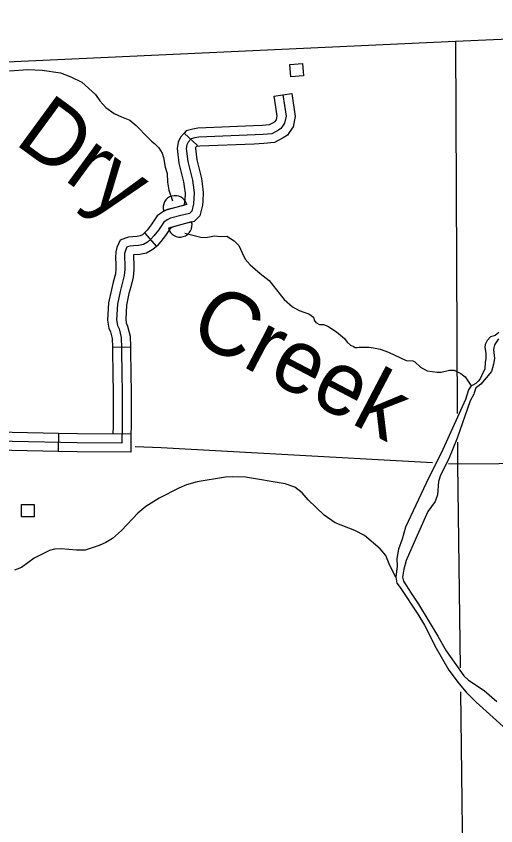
# Model space of a CAD drawing. Extents: x 1369885 to 1370219, y 379980 to 380218.
# Drawn here: x 1370011.52 to 1370027.37, y 380094.55 to 380121.32 of the extents above; entities that cross this region are included whole.
import ezdxf

# ---------------------------------------------------------------- set-up
doc = ezdxf.new("R2010")
doc.units = 0
for name, color, linetype in [('Level 1', 7, 'Continuous'), ('Level 32', 7, 'Continuous'), ('Level 35', 7, 'Continuous'), ('Level 38', 7, 'Continuous'), ('Level 45', 7, 'Continuous'), ('Level 5', 7, 'Continuous'), ('Level 56', 7, 'Continuous')]:
    doc.layers.add(name, color=color, linetype=linetype)

msp = doc.modelspace()

# ---------------------------------------------------------------- linework, layer by layer
at = {"layer": 'Level 1'}
msp.add_lwpolyline([(1370004.498, 380119.502), (1370026.044, 380120.496), (1370044.91, 380121.323)], dxfattribs=at)
at = {"layer": 'Level 32'}
for p, q in [((1370012.919, 380107.526), (1370012.907, 380106.93)), ((1370015.315, 380107.499), (1370015.307, 380106.903))]:
    msp.add_line(p, q, dxfattribs=at)
for points in [[(1370012.919, 380107.526), (1370011.391, 380107.558), (1370010.822, 380107.575)], [(1370015.013, 380107.203), (1370013.539, 380107.215), (1370011.383, 380107.259), (1370008.599, 380107.343), (1370005.817, 380107.471), (1370004.191, 380107.531)], [(1370015.315, 380107.499), (1370013.543, 380107.514), (1370012.919, 380107.526)], [(1370012.907, 380106.93), (1370011.376, 380106.961), (1370010.804, 380106.978)], [(1370015.307, 380106.903), (1370013.534, 380106.917), (1370012.907, 380106.93)]]:
    msp.add_lwpolyline(points, dxfattribs=at)
at = {"layer": 'Level 35'}
for points in [[(1370011.296, 380119.518), (1370011.905, 380119.565), (1370012.381, 380119.54), (1370012.986, 380119.45), (1370013.33, 380119.314), (1370013.685, 380119.146), (1370014.138, 380118.737), (1370014.281, 380118.523), (1370014.48, 380118.299), (1370014.76, 380118.107), (1370015, 380117.995), (1370015.28, 380117.88), (1370015.488, 380117.704), (1370015.871, 380117.316), (1370015.998, 380117.188), (1370016.091, 380117.109), (1370016.235, 380116.969), (1370016.347, 380116.793), (1370016.395, 380116.645), (1370016.443, 380116.333), (1370016.515, 380116.117), (1370016.518, 380115.833), (1370016.564, 380115.572), (1370016.684, 380115.213)], [(1370017.096, 380114.148), (1370017.629, 380114.014), (1370017.788, 380114.001), (1370017.961, 380114.041), (1370018.077, 380114.061), (1370018.273, 380114.037), (1370018.482, 380114.047), (1370018.721, 380113.899), (1370018.879, 380113.736), (1370018.993, 380113.502), (1370019.084, 380113.287), (1370019.251, 380113.096), (1370019.59, 380112.814), (1370019.879, 380112.58)], [(1370019.879, 380112.58), (1370020.244, 380112.117), (1370020.383, 380111.954), (1370020.65, 380111.71), (1370020.87, 380111.591), (1370021.032, 380111.538), (1370021.195, 380111.476), (1370021.343, 380111.366), (1370021.371, 380111.276), (1370021.429, 380111.199), (1370021.543, 380111.132), (1370021.677, 380111.123), (1370021.825, 380111.075), (1370022.107, 380110.884), (1370022.373, 380110.67), (1370022.46, 380110.54), (1370022.575, 380110.444), (1370022.67, 380110.396), (1370022.723, 380110.363), (1370022.794, 380110.368), (1370022.861, 380110.382), (1370023.023, 380110.373), (1370023.176, 380110.382), (1370023.329, 380110.353), (1370023.553, 380110.315), (1370023.826, 380110.21), (1370024.413, 380109.933), (1370024.633, 380109.928), (1370024.699, 380109.895), (1370024.881, 380109.713), (1370025.105, 380109.596), (1370025.432, 380109.547), (1370025.568, 380109.551), (1370025.841, 380109.613), (1370025.993, 380109.613), (1370026.218, 380109.512), (1370026.356, 380109.398), (1370026.562, 380109.097)], [(1370027.469, 380110.868), (1370027.352, 380110.768), (1370027.201, 380110.718), (1370027.09, 380110.599), (1370027.019, 380110.461), (1370027.01, 380110.365), (1370027.039, 380110.179)], [(1370027.464, 380110.658), (1370027.33, 380110.452), (1370027.297, 380110.299), (1370027.326, 380110.004), (1370027.297, 380109.813), (1370027.228, 380109.575), (1370026.877, 380109.159), (1370026.777, 380109.082), (1370026.715, 380109.035), (1370026.691, 380108.968), (1370026.657, 380108.863), (1370026.652, 380108.82), (1370026.524, 380108.6), (1370026.1, 380107.368), (1370025.811, 380106.669), (1370025.549, 380106.143), (1370025.48, 380105.934), (1370025.449, 380105.499), (1370025.365, 380105.273), (1370025.129, 380104.939), (1370024.595, 380103.757), (1370024.415, 380103.329), (1370024.33, 380103.039), (1370024.285, 380102.769), (1370024.321, 380102.643), (1370024.579, 380102.243), (1370024.824, 380101.877), (1370025.456, 380100.823), (1370025.737, 380100.337), (1370026.318, 380099.51), (1370026.47, 380099.363), (1370026.993, 380099.02), (1370027.405, 380098.662)], [(1370027.039, 380110.179), (1370027.045, 380109.996), (1370027.02, 380109.887), (1370027.015, 380109.646), (1370026.944, 380109.527), (1370026.853, 380109.336), (1370026.791, 380109.259), (1370026.715, 380109.173), (1370026.619, 380109.125), (1370026.562, 380109.097), (1370026.476, 380108.963), (1370026.375, 380108.643), (1370025.626, 380106.999), (1370025.068, 380105.878), (1370024.393, 380104.424), (1370024.276, 380104.028), (1370024.159, 380103.695), (1370024.105, 380103.389), (1370024.114, 380103.137), (1370024.069, 380102.768), (1370024.102, 380102.578)], [(1370024.069, 380102.768), (1370023.871, 380103.164), (1370023.736, 380103.488), (1370023.557, 380103.707), (1370023.039, 380104.154), (1370022.709, 380104.315), (1370022.069, 380104.567), (1370021.7, 380104.823), (1370021.168, 380105.325), (1370020.971, 380105.562), (1370020.73, 380105.754), (1370020.413, 380105.864), (1370019.1, 380106.083), (1370018.682, 380106.094), (1370018.437, 380106.075), (1370017.508, 380105.923), (1370017.145, 380105.828), (1370016.898, 380105.721), (1370016.245, 380105.382), (1370015.809, 380105.106), (1370015.541, 380104.891), (1370014.998, 380104.316), (1370014.7, 380104.056), (1370014.486, 380103.922), (1370014.263, 380103.816), (1370013.798, 380103.67), (1370013.513, 380103.665), (1370013.007, 380103.71), (1370012.789, 380103.699), (1370012.623, 380103.65), (1370012.118, 380103.4), (1370011.699, 380103.096), (1370011.463, 380103.005)], [(1370024.102, 380102.578), (1370024.212, 380102.427), (1370024.799, 380101.548), (1370025.012, 380101.188), (1370025.278, 380100.67)], [(1370025.278, 380100.67), (1370025.359, 380100.497), (1370025.824, 380099.702), (1370026.164, 380099.242), (1370026.398, 380098.97), (1370026.73, 380098.637), (1370027.62, 380097.839)]]:
    msp.add_lwpolyline(points, dxfattribs=at)
at = {"layer": 'Level 38'}
for p, q in [((1370017.158, 380115.098), (1370016.392, 380114.883)), ((1370017.319, 380114.523), (1370016.553, 380114.309))]:
    msp.add_line(p, q, dxfattribs=at)
for centre, start, end in [((1370016.775, 380114.99), 15.6064, 195.6064), ((1370016.936, 380114.416), 195.6064, 15.6064)]:
    msp.add_arc(centre, 0.398, start, end, dxfattribs=at)
at = {"layer": 'Level 45'}
for p, q in [((1370020.04, 380118.675), (1370020.63, 380118.764)), ((1370017.074, 380117.457), (1370017.512, 380117.052)), ((1370015.76, 380114.158), (1370016.157, 380113.712)), ((1370014.702, 380110.38), (1370015.298, 380110.394))]:
    msp.add_line(p, q, dxfattribs=at)
for points in [[(1370020.335, 380118.719), (1370020.441, 380118.019), (1370020.391, 380117.78), (1370020.303, 380117.652), (1370020.273, 380117.611), (1370020.193, 380117.557), (1370019.969, 380117.437), (1370019.685, 380117.406), (1370017.556, 380117.325), (1370017.428, 380117.301), (1370017.303, 380117.265), (1370017.2, 380117.155), (1370017.16, 380117.074), (1370017.144, 380116.946), (1370017.194, 380116.517), (1370017.348, 380115.896), (1370017.369, 380115.733), (1370017.406, 380115.481), (1370017.384, 380115.113), (1370017.326, 380114.874), (1370017.254, 380114.802), (1370016.962, 380114.73), (1370016.623, 380114.642), (1370016.515, 380114.594), (1370016.399, 380114.51), (1370016.219, 380114.25), (1370016.075, 380114.059), (1370015.972, 380113.947), (1370015.864, 380113.851), (1370015.724, 380113.775), (1370015.56, 380113.739), (1370015.396, 380113.727), (1370015.284, 380113.719), (1370015.232, 380113.703), (1370015.179, 380113.682), (1370015.131, 380113.578), (1370015.105, 380113.48), (1370015.097, 380113.331), (1370015.113, 380113.132), (1370015.113, 380112.945), (1370015.093, 380112.745), (1370014.957, 380112.222), (1370014.873, 380111.805), (1370014.841, 380111.285), (1370014.873, 380111.093), (1370014.921, 380110.981), (1370014.993, 380110.701), (1370015.001, 380110.35), (1370015.013, 380109.403), (1370015.021, 380108.967), (1370015.02, 380108.447), (1370015.021, 380107.771), (1370015.013, 380107.203)], [(1370020.04, 380118.675), (1370020.138, 380118.028), (1370020.111, 380117.9), (1370020.062, 380117.828), (1370020.039, 380117.812), (1370019.879, 380117.727), (1370019.663, 380117.703), (1370019.369, 380117.692)], [(1370020.63, 380118.764), (1370020.744, 380118.011), (1370020.671, 380117.661), (1370020.547, 380117.48), (1370020.484, 380117.393), (1370020.347, 380117.301), (1370020.059, 380117.147), (1370019.707, 380117.108), (1370019.391, 380117.096)], [(1370019.369, 380117.692), (1370017.523, 380117.622), (1370017.36, 380117.592), (1370017.141, 380117.53), (1370017.074, 380117.457)], [(1370017.074, 380117.457), (1370016.952, 380117.326), (1370016.871, 380117.161), (1370016.844, 380116.947), (1370016.9, 380116.464), (1370017.054, 380115.841), (1370017.073, 380115.692), (1370017.106, 380115.468), (1370017.093, 380115.244)], [(1370017.512, 380117.052), (1370017.45, 380116.985), (1370017.445, 380116.944), (1370017.488, 380116.57), (1370017.641, 380115.951), (1370017.664, 380115.774), (1370017.705, 380115.494), (1370017.689, 380115.21)], [(1370019.391, 380117.096), (1370017.59, 380117.028), (1370017.497, 380117.01), (1370017.465, 380117.001), (1370017.512, 380117.052)], [(1370017.093, 380115.244), (1370017.088, 380115.158), (1370017.065, 380115.063), (1370016.889, 380115.019), (1370016.524, 380114.925), (1370016.365, 380114.854), (1370016.183, 380114.722), (1370015.977, 380114.425), (1370015.846, 380114.25), (1370015.763, 380114.16), (1370015.76, 380114.158)], [(1370017.689, 380115.21), (1370017.681, 380115.069), (1370017.596, 380114.722), (1370017.406, 380114.532), (1370017.035, 380114.441), (1370016.721, 380114.36), (1370016.665, 380114.334), (1370016.615, 380114.299), (1370016.461, 380114.076), (1370016.305, 380113.867), (1370016.181, 380113.733), (1370016.157, 380113.712)], [(1370015.76, 380114.158), (1370015.691, 380114.096), (1370015.619, 380114.057), (1370015.517, 380114.035), (1370015.375, 380114.024), (1370015.229, 380114.014), (1370015.134, 380113.985), (1370014.958, 380113.916), (1370014.849, 380113.679), (1370014.809, 380113.526), (1370014.798, 380113.328), (1370014.814, 380113.12), (1370014.814, 380112.96), (1370014.798, 380112.798), (1370014.727, 380112.524)], [(1370016.157, 380113.712), (1370016.036, 380113.605), (1370015.829, 380113.492), (1370015.603, 380113.443), (1370015.418, 380113.429), (1370015.401, 380113.428), (1370015.396, 380113.334), (1370015.411, 380113.144), (1370015.411, 380112.93), (1370015.387, 380112.693), (1370015.305, 380112.374)], [(1370014.727, 380112.524), (1370014.666, 380112.289), (1370014.576, 380111.843), (1370014.541, 380111.269), (1370014.585, 380111.009), (1370014.638, 380110.885), (1370014.695, 380110.66), (1370014.702, 380110.38)], [(1370015.305, 380112.374), (1370015.248, 380112.155), (1370015.169, 380111.766), (1370015.141, 380111.301), (1370015.161, 380111.178), (1370015.204, 380111.078), (1370015.29, 380110.742), (1370015.298, 380110.394)], [(1370014.702, 380110.38), (1370014.702, 380110.344), (1370014.714, 380109.398), (1370014.722, 380108.964), (1370014.721, 380108.447), (1370014.722, 380108.287)], [(1370015.298, 380110.394), (1370015.299, 380110.355), (1370015.311, 380109.407), (1370015.319, 380108.969), (1370015.318, 380108.446), (1370015.318, 380108.287)], [(1370014.722, 380108.287), (1370014.722, 380107.773), (1370014.719, 380107.504)], [(1370015.318, 380108.287), (1370015.319, 380107.769), (1370015.315, 380107.499)]]:
    msp.add_lwpolyline(points, dxfattribs=at)
at = {"layer": 'Level 5'}
for points in [[(1370026.044, 380120.496), (1370026.1, 380108.188)], [(1370025.284, 380106.55), (1370016.318, 380107.052), (1370015.458, 380107.081)], [(1370026.105, 380107.237), (1370026.108, 380106.504)], [(1370026.108, 380106.504), (1370025.813, 380106.521)], [(1370043.904, 380106.648), (1370026.108, 380106.504)], [(1370026.108, 380106.504), (1370026.194, 380099.78)], [(1370026.204, 380098.983), (1370026.308, 380090.821)]]:
    msp.add_lwpolyline(points, dxfattribs=at)
at = {"layer": 'Level 56'}
for points in [[(1370020.6, 380119.317), (1370020.568, 380119.73), (1370020.982, 380119.763), (1370021.014, 380119.35)], [(1370011.699, 380104.763), (1370011.699, 380105.177), (1370012.114, 380105.177), (1370012.114, 380104.763)]]:
    msp.add_lwpolyline(points, close=True, dxfattribs=at)

# ---------------------------------------------------------------- texts
at = {"layer": 'Level 35'}
for s, rotation, p in [('Dry', 323.8231, (1370011.429, 380117.129)), ('Creek', 332.3375, (1370017.152, 380110.708))]:
    msp.add_text(s, height=2.1003, rotation=rotation, dxfattribs=at).set_placement(p)

doc.saveas('drawing.dxf')
